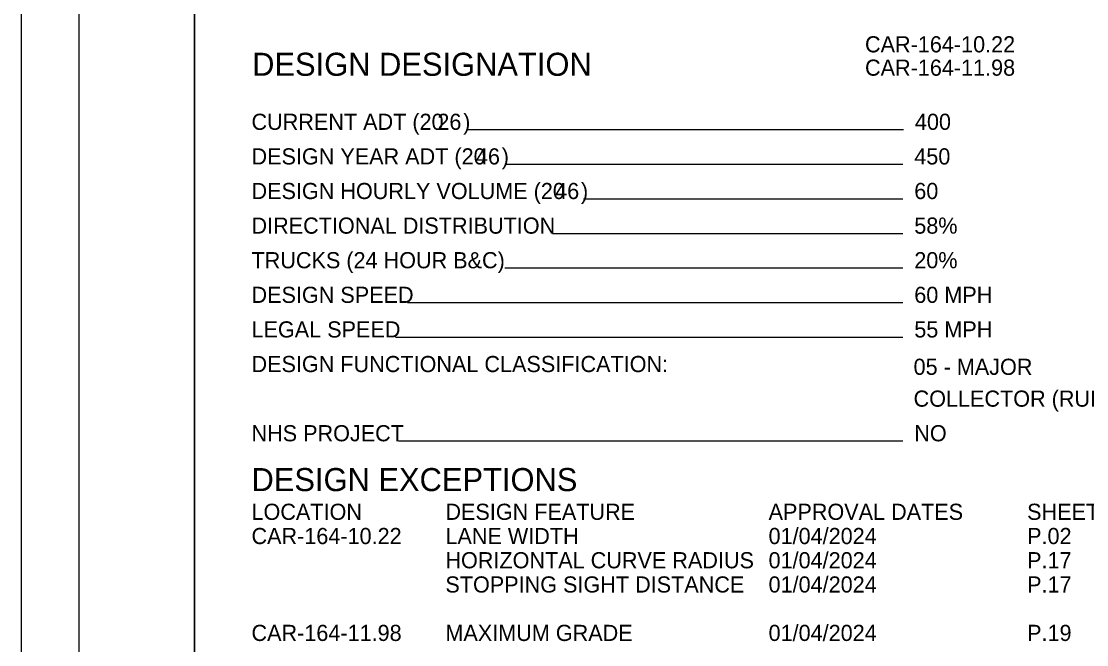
# Model space of a CAD drawing. Extents: x -3.6 to 34, y 0 to 32.8.
# Drawn here: x 0 to 9.23, y 5.34 to 10.75 of the extents above; entities that cross this region are included whole.
import ezdxf

# ---------------------------------------------------------------- set-up
doc = ezdxf.new("R2010")
doc.units = 0
for name, color, linetype in [('SH_Border', 7, 'Continuous'), ('SH_Cut_Line', 7, 'Continuous'), ('SH_Data', 7, 'Continuous'), ('SH_Text', 7, 'Continuous')]:
    doc.layers.add(name, color=color, linetype=linetype)

msp = doc.modelspace()

# ---------------------------------------------------------------- linework, layer by layer
at = {"layer": 'SH_Border'}
for points in [[(0.5, 21.5), (1.5, 21.5), (1.5, 0.5), (0.5, 0.5)], [(1.5, 21.5), (33.5, 21.5), (33.5, 0.5), (1.5, 0.5)]]:
    msp.add_lwpolyline(points, close=True, dxfattribs=at)
at = {"layer": 'SH_Cut_Line'}
msp.add_lwpolyline([(0, 0), (34, 0), (34, 22), (0, 22)], close=True, dxfattribs=at)
at = {"layer": 'SH_Data'}
for p, q in [((7.6424, 9.8062), (3.871, 9.8062)), ((7.6368, 9.5062), (4.1885, 9.5062)), ((7.6368, 9.2062), (4.8723, 9.2062)), ((7.6368, 8.9062), (4.6037, 8.9062)), ((7.6368, 8.6062), (4.1885, 8.6062)), ((7.6368, 8.3062), (3.346, 8.3062)), ((7.6368, 8.0062), (3.2422, 8.0062)), ((7.6368, 7.1062), (3.2669, 7.1062))]:
    msp.add_line(p, q, dxfattribs=at)

# ---------------------------------------------------------------- texts
msp.add_text('DESIGN DESIGNATION', height=0.2, dxfattribs=at).set_placement((2, 10.2747))
at = {"layer": 'SH_Text'}
for s, height, p in [('CAR-164-10.22', 0.14, (7.3099, 10.478)), ('CAR-164-11.98', 0.14, (7.3099, 10.2755)), ('CURRENT ADT (20', 0.14, (1.9944, 9.8062)), ('26', 0.14, (3.6047, 9.8062)), (')', 0.14, (3.8282, 9.8062)), ('400   ', 0.14, (7.7424, 9.8062)), ('DESIGN YEAR ADT (20', 0.14, (1.9944, 9.5062)), ('46', 0.14, (3.939, 9.5062)), (')', 0.14, (4.1625, 9.5062)), ('450   ', 0.14, (7.7368, 9.5062)), ('DESIGN HOURLY VOLUME (20', 0.14, (1.9944, 9.2062)), ('46', 0.14, (4.6254, 9.2062)), (')', 0.14, (4.8488, 9.2062)), ('60    ', 0.14, (7.7368, 9.2062)), ('DIRECTIONAL DISTRIBUTION', 0.14, (1.9944, 8.9062)), ('58%   ', 0.14, (7.7368, 8.9062)), ('TRUCKS (24 HOUR B&C)', 0.14, (1.9944, 8.6062)), ('20%   ', 0.14, (7.7368, 8.6062)), ('DESIGN SPEED', 0.14, (1.9944, 8.3062)), ('60 MPH', 0.14, (7.7368, 8.3062)), ('LEGAL SPEED', 0.14, (1.9944, 8.0062)), ('55 MPH', 0.14, (7.7368, 8.0062)), ('DESIGN FUNCTIONAL CLASSIFICATION:', 0.14, (1.9944, 7.7062)), ('05 - MAJOR                                      ', 0.14, (7.7308, 7.6823)), ('COLLECTOR (RURAL)                               ', 0.14, (7.7308, 7.4062)), ('NHS PROJECT', 0.14, (1.9944, 7.1062)), ('NO    ', 0.14, (7.7368, 7.1062)), ('DESIGN EXCEPTIONS', 0.2, (1.9944, 6.6744)), ('LOCATION', 0.14, (1.9944, 6.4252)), ('DESIGN FEATURE', 0.14, (3.6744, 6.4252)), ('APPROVAL DATES', 0.14, (6.4744, 6.4252)), ('SHEET NUMBERS', 0.14, (8.7144, 6.4252)), ('CAR-164-10.22', 0.14, (1.9944, 6.2152)), ('LANE WIDTH', 0.14, (3.6744, 6.2152)), ('01/04/2024', 0.14, (6.4744, 6.2152)), ('P.02', 0.14, (8.7144, 6.2152)), ('HORIZONTAL CURVE RADIUS', 0.14, (3.6744, 6.0052)), ('01/04/2024', 0.14, (6.4744, 6.0052)), ('P.17', 0.14, (8.7144, 6.0052)), ('STOPPING SIGHT DISTANCE', 0.14, (3.6744, 5.7952)), ('01/04/2024', 0.14, (6.4744, 5.7952)), ('P.17', 0.14, (8.7144, 5.7952)), ('CAR-164-11.98', 0.14, (1.9944, 5.3752)), ('MAXIMUM GRADE', 0.14, (3.6744, 5.3752)), ('01/04/2024', 0.14, (6.4744, 5.3752)), ('P.19', 0.14, (8.7144, 5.3752))]:
    msp.add_text(s, height=height, dxfattribs=at).set_placement(p)

doc.saveas('drawing.dxf')
